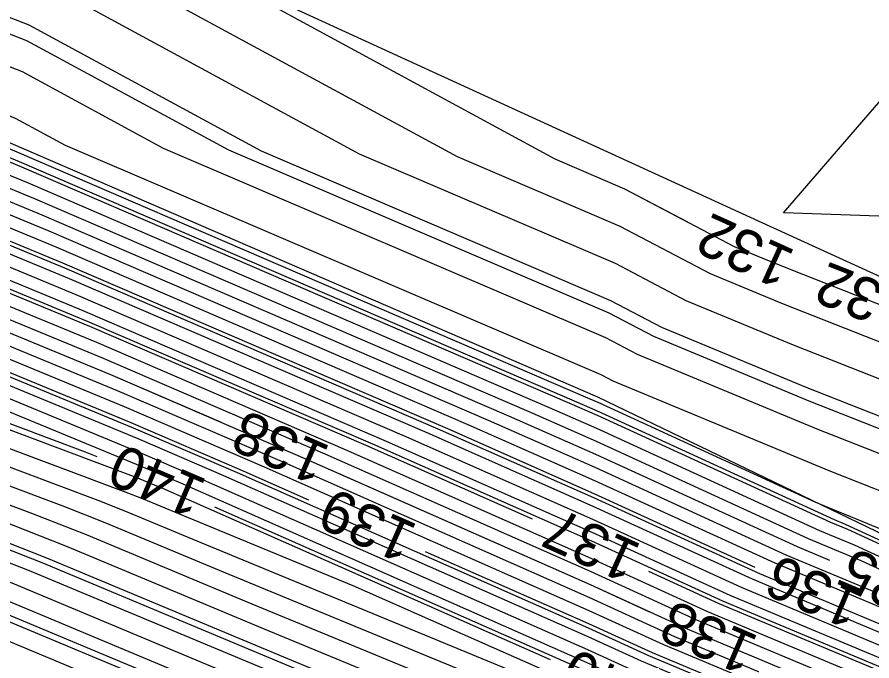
# Model space of a CAD drawing. Extents: x 2354170 to 2357230, y 866100 to 868290.
# Drawn here: x 2355153.3 to 2355193.44, y 867501.93 to 867532.18 of the extents above; entities that cross this region are included whole.
import ezdxf

# ---------------------------------------------------------------- set-up
doc = ezdxf.new("R2010")
doc.units = 0
for name, color, linetype in [('Default', 7, 'Continuous'), ('DTM Contours Major', 7, 'Continuous'), ('DTM Contours Major Text', 7, 'Continuous'), ('DTM Contours Minor', 7, 'Continuous'), ('DTM Contours Minor Text', 7, 'Continuous'), ('Exist DTM QL2 LIDAR Elevation Point', 7, 'Continuous'), ('PH Exist DTM Breakline', 7, 'Continuous')]:
    doc.layers.add(name, color=color, linetype=linetype)

msp = doc.modelspace()

# ---------------------------------------------------------------- linework, layer by layer
at = {"layer": 'Default'}
for points in [[(2355039.748, 867582.774), (2355057.845, 867572.501), (2355066.09, 867568.423), (2355075.66, 867563.616), (2355088.2, 867558.035), (2355090.288, 867556.998), (2355109.078, 867548.638), (2355117.687, 867544.873), (2355118.143, 867544.673), (2355135.4, 867537.032), (2355142.924, 867534.128), (2355152.971, 867529.837), (2355153.53, 867529.622), (2355160.154, 867526.024), (2355180.934, 867517.127), (2355182.414, 867516.349), (2355190.855, 867512.84), (2355199.936, 867509.264)], [(2355030.605, 867581.098), (2355048.031, 867569.375), (2355053.29, 867566.596), (2355066.627, 867561.622), (2355069.054, 867560.678), (2355086.4, 867553.004), (2355087.112, 867552.723), (2355112.383, 867541.543), (2355114.567, 867540.679), (2355114.963, 867540.522), (2355137.014, 867531.279), (2355139.122, 867530.678), (2355151.331, 867525.417), (2355153.823, 867524.387), (2355178.286, 867513.844), (2355180.51, 867512.86), (2355190.971, 867508.066), (2355192.601, 867507.384), (2355218.305, 867495.571)], [(2354995.047, 867580.65), (2355018.365, 867571.741), (2355022.674, 867569.867), (2355022.938, 867569.764), (2355041.304, 867560.814), (2355048.738, 867556.887), (2355052.264, 867555.571), (2355072.009, 867547.892), (2355078.691, 867544.936), (2355084.387, 867542.691), (2355094.899, 867538.04), (2355111.939, 867531.298), (2355115.029, 867530.075), (2355125.868, 867525.532), (2355139.851, 867521.546), (2355141.602, 867520.791), (2355158.318, 867513.884), (2355164.901, 867511.046), (2355180.153, 867504.304), (2355183.645, 867502.704), (2355196.955, 867497.127)], [(2355029.69, 867579.758), (2355040.479, 867572.499), (2355052.965, 867565.903), (2355065.601, 867561.19), (2355069.265, 867559.765), (2355085.849, 867552.427), (2355086.917, 867552.006), (2355111.135, 867541.292), (2355114.379, 867540.009), (2355114.968, 867539.776), (2355136.218, 867530.869), (2355139.174, 867530.026), (2355150.636, 867525.087), (2355154.144, 867523.637), (2355177.33, 867513.644), (2355180.485, 867512.249), (2355190.448, 867507.683), (2355192.912, 867506.651), (2355217.532, 867495.337)], [(2355043.958, 867577.984), (2355056.525, 867570.85), (2355067.342, 867565.501), (2355072.214, 867563.054), (2355087.851, 867556.095), (2355088.894, 867555.577), (2355112.103, 867545.25), (2355116.28, 867543.423), (2355116.501, 867543.327), (2355137.772, 867533.908), (2355140.329, 867532.921), (2355153.012, 867527.504), (2355153.21, 867527.428), (2355155.552, 867526.156), (2355180.709, 867515.384), (2355181.269, 867515.089), (2355191.411, 867510.874), (2355196.056, 867509.044)], [(2355062.336, 867577.188), (2355085.998, 867565.304), (2355089.249, 867563.857), (2355094.47, 867561.263), (2355100.002, 867558.802), (2355121.91, 867549.221), (2355123.07, 867548.714), (2355128.285, 867546.405), (2355150.708, 867537.749), (2355152.846, 867536.836), (2355154.489, 867536.205), (2355173.961, 867525.629), (2355181.609, 867522.355), (2355185.848, 867520.129), (2355189.188, 867518.74), (2355211.575, 867509.924)], [(2355028.633, 867577.026), (2355052.315, 867564.516), (2355063.549, 867560.326), (2355069.688, 867557.938), (2355084.748, 867551.275), (2355086.528, 867550.573), (2355108.637, 867540.792), (2355114.004, 867538.669), (2355114.977, 867538.283), (2355134.626, 867530.048), (2355139.278, 867528.721), (2355149.246, 867524.426), (2355154.786, 867522.137), (2355175.418, 867513.244), (2355180.434, 867511.027), (2355189.401, 867506.917), (2355193.534, 867505.186)], [(2355002.655, 867575.912), (2355019.366, 867569.527), (2355021.702, 867568.511), (2355022.012, 867568.39), (2355043.608, 867557.866), (2355048.087, 867555.5), (2355050.212, 867554.707), (2355072.431, 867546.066), (2355077.59, 867543.784), (2355083.997, 867541.258), (2355092.402, 867537.54), (2355111.563, 867529.958), (2355115.038, 867528.583), (2355124.276, 867524.711), (2355139.955, 867520.242), (2355140.213, 867520.131), (2355158.96, 867512.383), (2355162.989, 867510.647), (2355180.102, 867503.082), (2355182.598, 867501.938), (2355197.577, 867495.662)], [(2355029.785, 867575.552), (2355051.989, 867563.822), (2355062.523, 867559.893), (2355069.899, 867557.025), (2355084.197, 867550.699), (2355086.333, 867549.857), (2355107.388, 867540.542), (2355113.816, 867537.999), (2355114.982, 867537.537), (2355133.83, 867529.637), (2355139.331, 867528.069), (2355148.551, 867524.095), (2355155.107, 867521.386), (2355174.462, 867513.045), (2355180.408, 867510.416), (2355188.878, 867506.534), (2355193.845, 867504.453)], [(2355196.022, 867499.325), (2355185.215, 867503.853), (2355180.229, 867506.138), (2355167.77, 867511.646), (2355157.355, 867516.135), (2355143.687, 867521.783), (2355139.695, 867523.503), (2355128.257, 867526.764), (2355115.015, 867532.314), (2355112.502, 867533.308), (2355098.646, 867538.791), (2355084.971, 867544.841), (2355080.343, 867546.665), (2355071.376, 867550.632), (2355055.342, 867556.868), (2355049.713, 867558.967), (2355037.849, 867565.235), (2355024.326, 867571.825), (2355024.132, 867571.901), (2355016.865, 867575.061)], [(2355194.778, 867502.255), (2355187.308, 867505.385), (2355180.331, 867508.582), (2355171.594, 867512.445), (2355156.07, 867519.136), (2355146.466, 867523.104), (2355139.487, 867526.112), (2355131.441, 867528.406), (2355114.996, 867535.299), (2355113.253, 867535.988), (2355103.641, 867539.791), (2355085.749, 867547.707), (2355082.545, 867548.97), (2355070.532, 867554.285), (2355059.445, 867558.597), (2355051.014, 867561.741), (2355033.241, 867571.131), (2355026.177, 867574.573)], [(2355063.587, 867574.266), (2355082.552, 867564.741), (2355088.899, 867561.917), (2355093.076, 867559.842), (2355103.027, 867555.414), (2355120.503, 867547.772), (2355121.428, 867547.367), (2355130.657, 867543.28), (2355148.114, 867536.542), (2355152.888, 867534.503), (2355154.169, 867534.011), (2355169.359, 867525.761), (2355181.384, 867520.612), (2355184.703, 867518.869), (2355189.744, 867516.774), (2355207.695, 867509.704)], [(2354998.866, 867573.748), (2355010.208, 867572.11), (2355019.866, 867568.42), (2355021.216, 867567.833), (2355021.55, 867567.703), (2355044.76, 867556.392), (2355047.762, 867554.806), (2355049.186, 867554.275), (2355072.643, 867545.153), (2355077.039, 867543.207), (2355083.803, 867540.541), (2355091.153, 867537.289), (2355111.376, 867529.288), (2355115.043, 867527.837), (2355123.48, 867524.301), (2355138.516, 867520.014), (2355140.061, 867519.404), (2355144.636, 867517.685), (2355159.281, 867511.633), (2355162.033, 867510.447), (2355180.076, 867502.471), (2355182.075, 867501.555), (2355197.888, 867494.929)], [(2355195.089, 867501.523), (2355186.785, 867505.002), (2355180.306, 867507.971), (2355170.638, 867512.245), (2355156.392, 867518.385), (2355145.772, 867522.774), (2355139.539, 867525.46), (2355130.645, 867527.995), (2355115.001, 867534.553), (2355113.065, 867535.318), (2355102.393, 867539.541), (2355085.555, 867546.99), (2355081.995, 867548.394), (2355070.743, 867553.372), (2355058.419, 867558.165), (2355050.689, 867561.048), (2355034.393, 867569.657), (2355025.715, 867573.886)], [(2355048.169, 867573.195), (2355055.206, 867569.2), (2355068.594, 867562.579), (2355068.769, 867562.491), (2355086.8, 867554.466), (2355087.501, 867554.156), (2355087.501, 867554.156), (2355114.881, 867542.043), (2355114.942, 867542.019), (2355114.954, 867542.014), (2355138.607, 867532.1), (2355139.018, 867531.983), (2355152.72, 867526.078), (2355153.181, 867525.888), (2355180.198, 867514.243), (2355180.561, 867514.083), (2355190.76, 867509.409), (2355191.967, 867508.907), (2355192.176, 867508.825), (2355218.458, 867497.985)], [(2355017.865, 867572.848), (2355023.16, 867570.545), (2355023.401, 867570.451), (2355040.152, 867562.287), (2355049.063, 867557.58), (2355053.29, 867556.004), (2355071.798, 867548.806), (2355079.242, 867545.512), (2355084.581, 867543.407), (2355096.148, 867538.29), (2355112.126, 867531.968), (2355115.024, 867530.822), (2355126.665, 867525.943), (2355139.799, 867522.198), (2355142.297, 867521.122), (2355157.997, 867514.634), (2355165.857, 867511.246), (2355180.178, 867504.915), (2355184.168, 867503.087), (2355196.644, 867497.86)], [(2355195.711, 867500.057), (2355185.738, 867504.236), (2355180.255, 867506.749), (2355168.726, 867511.846), (2355157.034, 867516.885), (2355144.382, 867522.113), (2355139.643, 867524.155), (2355129.053, 867527.174), (2355115.01, 867533.06), (2355112.69, 867533.978), (2355099.895, 867539.041), (2355085.165, 867545.557), (2355080.893, 867547.241), (2355071.165, 867551.545), (2355056.368, 867557.3), (2355050.038, 867559.661), (2355036.697, 867566.709), (2355024.789, 867572.512), (2355024.618, 867572.579)], [(2355194.467, 867502.988), (2355187.831, 867505.768), (2355180.357, 867509.194), (2355172.55, 867512.645), (2355155.749, 867519.886), (2355147.161, 867523.435), (2355139.435, 867526.765), (2355132.238, 867528.816), (2355114.991, 867536.045), (2355113.441, 867536.658), (2355104.89, 867540.042), (2355085.944, 867548.423), (2355083.096, 867549.546), (2355070.321, 867555.198), (2355060.471, 867559.029), (2355051.339, 867562.435), (2355032.089, 867572.605)], [(2355001.207, 867570.699), (2355017.762, 867568.308), (2355020.366, 867567.313), (2355020.73, 867567.155), (2355021.087, 867567.016), (2355045.912, 867554.918), (2355047.437, 867554.112), (2355048.16, 867553.843), (2355072.854, 867544.239), (2355076.489, 867542.631), (2355083.608, 867539.825), (2355089.904, 867537.039), (2355111.188, 867528.618), (2355115.048, 867527.091), (2355122.684, 867523.89), (2355136.293, 867520.011), (2355140.195, 867518.469), (2355151.754, 867514.126), (2355159.602, 867510.883), (2355161.077, 867510.247), (2355180.05, 867501.86), (2355181.552, 867501.172), (2355198.199, 867494.196)], [(2355184.789, 867522.546), (2355181.834, 867524.097), (2355178.563, 867525.498), (2355161.009, 867535.032), (2355164.616, 867538.845), (2355173.269, 867547.841), (2355168.167, 867552.236), (2355157.704, 867557.272), (2355146.74, 867564.68), (2355145.524, 867567.247), (2355151.271, 867564.671), (2355154.577, 867563.085), (2355164.274, 867557.863)], [(2355070.126, 867550.287), (2355071.587, 867549.719), (2355079.792, 867546.089), (2355084.776, 867544.124), (2355097.397, 867538.54), (2355112.314, 867532.638), (2355115.02, 867531.568), (2355127.461, 867526.353), (2355139.747, 867522.851), (2355142.992, 867521.452), (2355157.676, 867515.384), (2355162.877, 867513.143)], [(2355177.5, 867508.589), (2355169.682, 867512.045), (2355156.713, 867517.635), (2355145.077, 867522.443), (2355139.591, 867524.808), (2355129.849, 867527.585), (2355115.005, 867533.806), (2355112.877, 867534.648), (2355101.144, 867539.291), (2355085.36, 867546.274), (2355085.011, 867546.411)], [(2355074.048, 867546.171), (2355078.14, 867544.36), (2355084.192, 867541.974), (2355093.651, 867537.79), (2355111.751, 867530.628), (2355115.034, 867529.329), (2355125.072, 867525.122), (2355139.903, 867520.894), (2355140.907, 867520.461), (2355158.639, 867513.134), (2355163.945, 867510.847), (2355166.979, 867509.506)], [(2355099.408, 867545.678), (2355109.886, 867541.042), (2355114.192, 867539.339), (2355114.972, 867539.03), (2355135.422, 867530.458), (2355139.226, 867529.374), (2355149.941, 867524.756), (2355154.465, 867522.887), (2355176.374, 867513.444), (2355180.459, 867511.638), (2355189.925, 867507.3), (2355191.442, 867506.665)], [(2355095.736, 867544.894), (2355106.139, 867540.292), (2355113.628, 867537.328), (2355114.987, 867536.791), (2355133.034, 867529.227), (2355139.383, 867527.417), (2355147.856, 867523.765), (2355155.428, 867520.636), (2355173.506, 867512.845), (2355180.383, 867509.805), (2355187.942, 867506.34)], [(2355075.387, 867541.479), (2355083.219, 867538.391), (2355087.406, 867536.539), (2355110.812, 867527.278), (2355115.057, 867525.598), (2355121.092, 867523.069), (2355131.846, 867520.003), (2355140.464, 867516.599), (2355158.655, 867509.764), (2355159.218, 867509.544), (2355160.871, 867508.852), (2355169.056, 867505.475), (2355179.999, 867500.637), (2355180.505, 867500.406), (2355198.821, 867492.731)], [(2355199.132, 867491.999), (2355179.982, 867500.023), (2355179.974, 867500.026), (2355179.803, 867500.102), (2355161.933, 867507.475), (2355158.324, 867508.984), (2355157.096, 867509.466), (2355140.598, 867515.664), (2355129.622, 867520), (2355120.295, 867522.659), (2355115.062, 867524.852), (2355110.625, 867526.608), (2355086.157, 867536.289), (2355083.024, 867537.675), (2355074.837, 867540.902)], [(2355075.489, 867539.058), (2355082.635, 867536.242), (2355083.66, 867535.788), (2355110.249, 867525.268), (2355115.071, 867523.36), (2355118.703, 867521.838), (2355125.176, 867519.992), (2355140.867, 867513.794), (2355153.977, 867508.868), (2355156.537, 867507.865), (2355164.057, 867504.72), (2355179.317, 867498.424), (2355181.309, 867497.592), (2355194.726, 867492.64)], [(2355085.248, 867538.296), (2355088.655, 867536.789), (2355111, 867527.948), (2355115.053, 867526.344), (2355121.888, 867523.48), (2355134.069, 867520.007), (2355140.33, 867517.534), (2355158.871, 867510.568), (2355159.923, 867510.133), (2355160.121, 867510.047), (2355178.336, 867501.995)], [(2355075.248, 867536.875), (2355082.374, 867535.497), (2355082.449, 867535.477), (2355082.497, 867535.467), (2355082.53, 867535.459), (2355082.7, 867535.424), (2355110.061, 867524.598), (2355115.076, 867522.614), (2355117.907, 867521.427), (2355122.952, 867519.989), (2355141.002, 867512.859), (2355152.417, 867508.57), (2355155.644, 867507.306), (2355165.119, 867503.342), (2355178.986, 867497.621), (2355181.982, 867496.37), (2355199.705, 867489.829)], [(2355189.282, 867522.981), (2355201.223, 867536.803), (2355209.473, 867532.724), (2355212.412, 867530.923), (2355216.802, 867529.128), (2355229.02, 867521.352), (2355213.46, 867522.141), (2355189.282, 867522.981)], [(2355143.722, 867536.028), (2355145.519, 867535.335), (2355152.929, 867532.17), (2355153.849, 867531.817), (2355164.756, 867525.893), (2355181.159, 867518.869), (2355183.559, 867517.609), (2355190.3, 867514.807), (2355203.816, 867509.484), (2355216.916, 867504.081), (2355224.347, 867501.177), (2355226.666, 867500.212), (2355235.349, 867496.169)], [(2355131.737, 867534.235), (2355137.811, 867531.69), (2355139.07, 867531.331), (2355152.025, 867525.748), (2355153.502, 867525.137), (2355179.242, 867514.044), (2355180.536, 867513.472), (2355191.495, 867508.449), (2355192.29, 867508.116), (2355216.867, 867496.821), (2355218.972, 867495.953), (2355219.122, 867495.895), (2355223.326, 867494.145)], [(2355078.244, 867531.76), (2355082.735, 867530.572), (2355086.184, 867529.868), (2355088.6, 867529.248), (2355101.028, 867526.683), (2355109.686, 867523.258), (2355115.086, 867521.121), (2355116.315, 867520.606), (2355118.505, 867519.982), (2355141.27, 867510.989), (2355149.298, 867507.972), (2355153.857, 867506.187), (2355167.243, 867500.587), (2355178.323, 867496.015), (2355183.329, 867493.925), (2355197.882, 867488.554)], [(2355199.755, 867491.123), (2355199.443, 867491.266), (2355187.291, 867496.358), (2355180.636, 867498.814), (2355179.648, 867499.226), (2355162.995, 867506.097), (2355157.431, 867508.425), (2355155.536, 867509.167), (2355140.733, 867514.729), (2355127.399, 867519.996), (2355119.499, 867522.248), (2355115.067, 867524.106), (2355110.437, 867525.938), (2355106.638, 867527.441)], [(2355281.402, 867485.009), (2355270.745, 867487.676), (2355266.895, 867488.919), (2355257.26, 867493.718), (2355254.94, 867494.647), (2355233.232, 867505.386), (2355231.086, 867509.67), (2355215.92, 867510.328), (2355215.348, 867510.357), (2355214.87, 867510.374), (2355190.247, 867520.071)], [(2355119.972, 867515.213), (2355127.354, 867513.84), (2355141.674, 867508.184), (2355144.62, 867507.077), (2355151.176, 867504.508), (2355170.429, 867496.455), (2355177.33, 867493.607), (2355185.348, 867490.259), (2355195.147, 867486.643), (2355205.884, 867482.442), (2355213.315, 867479.737)], [(2355168.38, 867510.753), (2355180.204, 867505.527), (2355184.692, 867503.47), (2355196.333, 867498.592), (2355209.026, 867492.759), (2355219.469, 867488.318), (2355222.651, 867486.982), (2355228.289, 867484.546), (2355237.789, 867480.557), (2355247.28, 867476.66), (2355251.097, 867474.782), (2355257.854, 867471.707), (2355260.013, 867470.748)], [(2355148.153, 867509.287), (2355150.858, 867508.271), (2355154.75, 867506.746), (2355166.181, 867501.965), (2355178.654, 867496.818), (2355182.655, 867495.147), (2355198.794, 867489.192), (2355201.418, 867488.165), (2355209.722, 867485.142), (2355219.926, 867480.803), (2355220.228, 867480.676), (2355221.755, 867480.016), (2355225.573, 867476.529), (2355235.92, 867474.071), (2355240.516, 867472.183)], [(2355172.467, 867507.08), (2355180.127, 867503.693), (2355183.122, 867502.321), (2355197.266, 867496.394), (2355206.706, 867492.056), (2355219.574, 867486.584), (2355222.092, 867485.527), (2355229.041, 867482.524), (2355234.301, 867480.316), (2355246.012, 867475.507), (2355250.722, 867473.189), (2355255.22, 867471.142), (2355264.145, 867467.178)], [(2355274.557, 867466.013), (2355269.31, 867468.402), (2355266.138, 867469.762), (2355260.488, 867472.272), (2355251.472, 867476.375), (2355248.548, 867477.813), (2355241.278, 867480.799), (2355227.537, 867486.567), (2355223.21, 867488.438), (2355219.363, 867490.053), (2355211.345, 867493.462), (2355195.4, 867500.79), (2355186.261, 867504.619), (2355182.971, 867506.127)], [(2355152.963, 867505.627), (2355168.305, 867499.21), (2355177.992, 867495.213), (2355184.002, 867492.703), (2355196.97, 867487.917)], [(2355196.058, 867487.28), (2355184.675, 867491.481), (2355177.661, 867494.41), (2355169.367, 867497.832), (2355152.07, 867505.068)], [(2355150.283, 867503.949), (2355171.491, 867495.077), (2355176.999, 867492.805), (2355186.021, 867489.037), (2355194.235, 867486.006)]]:
    msp.add_lwpolyline(points, dxfattribs=at)
at = {"layer": 'DTM Contours Major'}
for points in [[(2355063.712, 867547.241), (2355072.994, 867543.631), (2355076.122, 867542.247), (2355083.478, 867539.347), (2355089.071, 867536.872), (2355111.063, 867528.171), (2355115.051, 867526.593), (2355122.153, 867523.616), (2355134.81, 867520.008), (2355140.285, 867517.846), (2355156.499, 867511.754), (2355157.043, 867511.529)], [(2355099.408, 867545.678), (2355109.886, 867541.042), (2355114.192, 867539.339), (2355114.972, 867539.03), (2355135.422, 867530.458), (2355139.226, 867529.374), (2355149.941, 867524.756), (2355154.465, 867522.887), (2355176.374, 867513.444), (2355180.459, 867511.638), (2355189.925, 867507.3), (2355191.442, 867506.665)], [(2355162.562, 867509.176), (2355180.033, 867501.452), (2355181.203, 867500.916), (2355198.406, 867493.708), (2355203.87, 867491.197), (2355219.703, 867484.464), (2355221.408, 867483.749), (2355229.96, 867480.053), (2355230.037, 867480.021), (2355244.462, 867474.097), (2355250.263, 867471.242), (2355252.002, 867470.451), (2355254.306, 867469.428)]]:
    msp.add_lwpolyline(points, dxfattribs=at)
at = {"layer": 'DTM Contours Minor'}
for points in [[(2354998.582, 867581.131), (2355017.365, 867573.955), (2355023.646, 867571.223), (2355023.864, 867571.138), (2355039.001, 867563.761), (2355049.388, 867558.274), (2355054.316, 867556.436), (2355071.587, 867549.719), (2355079.792, 867546.089), (2355084.776, 867544.124), (2355097.397, 867538.54), (2355112.314, 867532.638), (2355115.02, 867531.568), (2355127.461, 867526.353), (2355139.747, 867522.851), (2355142.992, 867521.452), (2355157.676, 867515.384), (2355166.814, 867511.446), (2355180.204, 867505.527), (2355182.997, 867504.246)], [(2355025.557, 867567.271), (2355042.84, 867558.848), (2355048.304, 867555.962), (2355050.896, 867554.995), (2355072.291, 867546.675), (2355077.957, 867544.168), (2355084.127, 867541.735), (2355093.234, 867537.706), (2355111.688, 867530.405), (2355115.035, 867529.081), (2355124.807, 867524.985), (2355139.92, 867520.676), (2355140.676, 867520.351), (2355158.746, 867512.884), (2355163.627, 867510.78), (2355180.119, 867503.489), (2355182.947, 867502.193), (2355197.37, 867496.15), (2355206.448, 867491.978), (2355210.008, 867490.464)], [(2355190.247, 867520.071), (2355188.632, 867520.707), (2355186.993, 867521.389), (2355181.834, 867524.097), (2355178.563, 867525.498), (2355161.009, 867535.032), (2355164.616, 867538.845), (2355173.269, 867547.841), (2355168.167, 867552.236), (2355157.704, 867557.272), (2355146.74, 867564.68), (2355145.524, 867567.247), (2355151.271, 867564.671), (2355154.577, 867563.085), (2355176.096, 867551.495), (2355177.71, 867550.573), (2355190.752, 867543.561), (2355192.788, 867542.602), (2355205.585, 867536.275), (2355212.782, 867531.865), (2355223.534, 867527.469), (2355235.694, 867519.73), (2355241.245, 867516.51), (2355247.284, 867514.129)], [(2355115.591, 867547.166), (2355118.626, 867545.839), (2355119.238, 867545.571), (2355133.819, 867539.115), (2355144.654, 867534.933), (2355152.943, 867531.392), (2355153.743, 867531.085), (2355163.222, 867525.936), (2355181.084, 867518.288), (2355183.177, 867517.189), (2355190.485, 867514.152), (2355202.522, 867509.411), (2355217.087, 867503.404), (2355223.911, 867500.737), (2355226.535, 867499.645), (2355241.683, 867492.593), (2355253.966, 867487.474), (2355260.351, 867484.508), (2355267.475, 867481.396), (2355284.39, 867476.569), (2355295.537, 867471.814), (2355300.054, 867470.541)], [(2355111.207, 867543.133), (2355114.049, 867541.876), (2355114.817, 867541.572), (2355114.957, 867541.517), (2355138.076, 867531.827), (2355139.053, 867531.548), (2355152.257, 867525.858), (2355153.395, 867525.388), (2355179.561, 867514.11), (2355180.544, 867513.675), (2355191.669, 867508.577), (2355192.186, 867508.36), (2355208.165, 867501.017), (2355218.801, 867496.63), (2355219.558, 867496.335), (2355225.225, 867493.976), (2355226.966, 867493.166), (2355252.869, 867482.371), (2355253.717, 867481.977), (2355268.595, 867475.479), (2355271.849, 867474.55), (2355295.1, 867464.632)], [(2355314.763, 867453.12), (2355298.575, 867457.547), (2355294.777, 867459.009), (2355293.478, 867459.583), (2355289.988, 867461.088), (2355269.138, 867470.58), (2355267.185, 867471.418), (2355263.706, 867472.963), (2355251.931, 867478.321), (2355250.098, 867479.223), (2355245.542, 867481.094), (2355226.618, 867489.039), (2355223.893, 867490.216), (2355219.235, 867492.172), (2355214.181, 867494.321), (2355194.259, 867503.476), (2355188.18, 867506.023), (2355180.374, 867509.601), (2355173.187, 867512.778), (2355155.535, 867520.386), (2355147.625, 867523.655), (2355139.4, 867527.199), (2355132.768, 867529.09), (2355130.416, 867530.076)], [(2355313.363, 867451.539), (2355300.128, 867455.159), (2355293.984, 867457.525), (2355291.882, 867458.452), (2355286.236, 867460.887), (2355269.295, 867468.6), (2355266.233, 867469.913), (2355260.78, 867472.335), (2355251.514, 867476.552), (2355248.689, 867477.942), (2355241.666, 867480.826), (2355227.454, 867486.792), (2355223.272, 867488.599), (2355219.352, 867490.245), (2355211.603, 867493.54), (2355195.296, 867501.034), (2355186.436, 867504.747), (2355180.289, 867507.564), (2355170, 867512.112), (2355156.606, 867517.885), (2355145.308, 867522.554), (2355139.573, 867525.025), (2355130.114, 867527.721), (2355128.897, 867528.232)], [(2355109.625, 867523.778), (2355109.811, 867523.704), (2355115.082, 867521.619), (2355116.845, 867520.88), (2355119.987, 867519.984), (2355141.181, 867511.612), (2355150.338, 867508.172), (2355154.453, 867506.56), (2355166.535, 867501.506), (2355178.544, 867496.551), (2355182.88, 867494.74), (2355198.49, 867488.979)], [(2355199.443, 867491.266), (2355187.291, 867496.358), (2355180.636, 867498.814), (2355179.648, 867499.226), (2355162.995, 867506.097), (2355157.431, 867508.425), (2355155.536, 867509.167), (2355140.733, 867514.729), (2355127.399, 867519.996), (2355123.47, 867521.116)], [(2355151.474, 867504.695), (2355170.075, 867496.914), (2355177.441, 867493.875), (2355185.124, 867490.666), (2355195.451, 867486.855)]]:
    msp.add_lwpolyline(points, dxfattribs=at)
at = {"layer": 'Exist DTM QL2 LIDAR Elevation Point'}
msp.add_line((2355159.973, 867510.017), (2355159.973, 867510.017), dxfattribs=at)
at = {"layer": 'PH Exist DTM Breakline'}
for points in [[(2355035.245, 867587.895), (2355062.077, 867577.792), (2355096.215, 867563.043), (2355125.204, 867550.464), (2355154.737, 867537.91), (2355188.097, 867522.603), (2355227.663, 867504.53)], [(2355219.015, 867495.786), (2355180.571, 867514.321), (2355138.993, 867532.299), (2355114.953, 867542.057), (2355068.64, 867562.47), (2355053.527, 867567.101), (2355028.202, 867577.578)]]:
    msp.add_lwpolyline(points, dxfattribs=at)

# ---------------------------------------------------------------- texts
at = {"layer": 'Default'}
for s, rotation, p in [('132', 155.6114, (2355189.921, 867521.177)), ('138', 156.5319, (2355168.088, 867511.979)), ('139', 156.1507, (2355172.18, 867508.3)), ('137', 155.7698, (2355182.7, 867507.367)), ('135', 155.9453, (2355196.651, 867505.47)), ('136', 157.1238, (2355193.159, 867505.216)), ('140', 156.5759, (2355183.56, 867500.782))]:
    msp.add_text(s, height=2, rotation=rotation, dxfattribs=at).set_placement(p)
at = {"layer": 'DTM Contours Major Text'}
for s, rotation, p in [('140', 156.91, (2355162.301, 867510.411)), ('135', 155.9453, (2355196.651, 867505.47))]:
    msp.add_text(s, height=2, rotation=rotation, dxfattribs=at).set_placement(p)
at = {"layer": 'DTM Contours Minor Text'}
for s, rotation, p in [('132', 158.5042, (2355195.493, 867519.08)), ('138', 156.6801, (2355188.196, 867503.061))]:
    msp.add_text(s, height=2, rotation=rotation, dxfattribs=at).set_placement(p)

doc.saveas('drawing.dxf')
